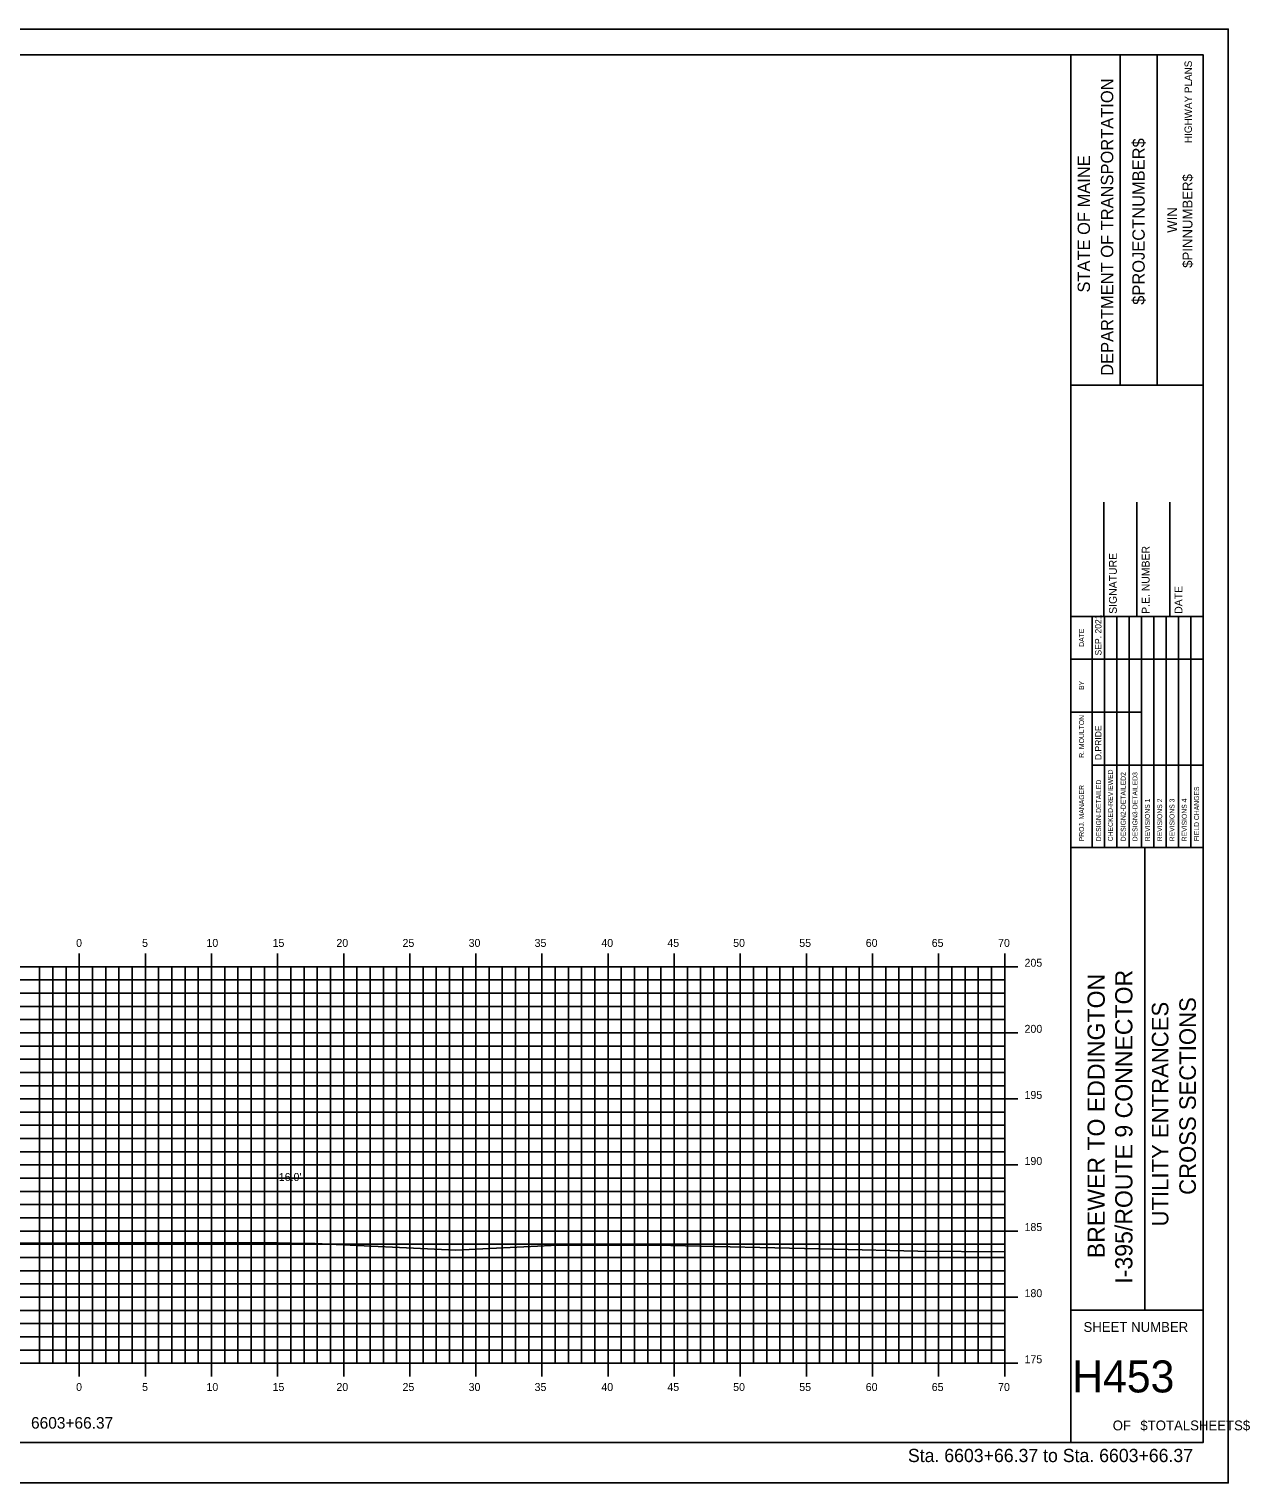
# Model space of a CAD drawing. Extents: x 1724848 to 1725020, y 459560 to 459670.
# Drawn here: x 1724927.7 to 1725020, y 459559.6 to 459669.6 of the extents above; entities that cross this region are included whole.
import ezdxf

# ---------------------------------------------------------------- set-up
doc = ezdxf.new("R2010")
doc.units = 0
for name, color, linetype in [('BORDER', 7, 'Continuous'), ('D_Roadway_SubGrade', 7, 'Continuous'), ('D_Text_Standard', 7, 'Continuous'), ('H_V ANNOTATION', 7, 'Continuous'), ('HIGHWAY_TITLE', 7, 'Continuous'), ('MAJOR', 7, 'Continuous'), ('MINOR', 7, 'Continuous'), ('PLOT BOUNDARY', 7, 'Continuous'), ('S_Roadway_Centerline', 7, 'Continuous')]:
    doc.layers.add(name, color=color, linetype=linetype)

msp = doc.modelspace()

# ---------------------------------------------------------------- linework, layer by layer
at = {"layer": 'BORDER'}
for p, q in [((1725006.5, 459562.61), (1725006.5, 459667.61)), ((1725010.23, 459642.61), (1725010.23, 459667.61)), ((1725013.02, 459642.61), (1725013.02, 459667.61)), ((1725006.5, 459642.61), (1725016.5, 459642.61)), ((1725009, 459625.12), (1725009, 459633.76)), ((1725011.5, 459625.12), (1725011.5, 459633.76)), ((1725014, 459625.12), (1725014, 459633.76)), ((1725006.5, 459625.12), (1725016.5, 459625.12)), ((1725006.5, 459607.62), (1725016.5, 459607.62)), ((1725012.09, 459572.62), (1725012.09, 459607.62)), ((1725006.5, 459572.62), (1725016.5, 459572.62))]:
    msp.add_line(p, q, dxfattribs=at)
msp.add_lwpolyline([(1724856.5, 459562.61), (1725016.5, 459562.61), (1725016.5, 459667.61), (1724856.5, 459667.61)], close=True, dxfattribs=at)
for points in [[(1725008.11, 459621.87), (1725008.11, 459625.12)], [(1725009.05, 459607.62), (1725009.05, 459625.12)], [(1725009.98, 459625.12), (1725009.98, 459607.62)], [(1725010.91, 459607.62), (1725010.91, 459625.12)], [(1725011.84, 459607.62), (1725011.84, 459625.12)], [(1725012.77, 459607.62), (1725012.77, 459625.12)], [(1725013.71, 459607.62), (1725013.71, 459625.12)], [(1725014.64, 459607.62), (1725014.64, 459625.12)], [(1725015.57, 459607.62), (1725015.57, 459625.12)], [(1725008.12, 459607.62), (1725008.12, 459624.41)], [(1725006.5, 459621.87), (1725016.5, 459621.87)], [(1725006.5, 459617.87), (1725008.12, 459617.87)], [(1725008.11, 459617.87), (1725011.84, 459617.87)], [(1725008.11, 459613.87), (1725016.5, 459613.87)]]:
    msp.add_lwpolyline(points, dxfattribs=at)
at = {"layer": 'D_Roadway_SubGrade'}
msp.add_line((1724946.5, 459577.72), (1724947.5, 459577.7), dxfattribs=at)
msp.add_lwpolyline([(1724931.5, 459577.71), (1724934.93, 459577.71), (1724945.04, 459577.73), (1724946.5, 459577.72)], dxfattribs=at)
at = {"layer": 'MAJOR'}
for p, q in [((1724931.5, 459599.61), (1724931.5, 459598.61)), ((1724936.5, 459599.61), (1724936.5, 459598.61)), ((1724941.5, 459599.61), (1724941.5, 459598.61)), ((1724946.5, 459599.61), (1724946.5, 459598.61)), ((1724951.5, 459599.61), (1724951.5, 459598.61)), ((1724956.5, 459599.61), (1724956.5, 459598.61)), ((1724961.5, 459599.61), (1724961.5, 459598.61)), ((1724966.5, 459599.61), (1724966.5, 459598.61)), ((1724971.5, 459599.61), (1724971.5, 459598.61)), ((1724976.5, 459599.61), (1724976.5, 459598.61)), ((1724981.5, 459599.61), (1724981.5, 459598.61)), ((1724986.5, 459599.61), (1724986.5, 459598.61)), ((1724991.5, 459599.61), (1724991.5, 459598.61)), ((1724996.5, 459599.61), (1724996.5, 459598.61)), ((1725001.5, 459599.61), (1725001.5, 459598.61)), ((1724861.5, 459598.61), (1725001.5, 459598.61)), ((1724861.5, 459598.61), (1725001.5, 459598.61)), ((1724931.5, 459568.61), (1724931.5, 459598.61)), ((1724936.5, 459568.61), (1724936.5, 459598.61)), ((1724941.5, 459568.61), (1724941.5, 459598.61)), ((1724946.5, 459568.61), (1724946.5, 459598.61)), ((1724951.5, 459568.61), (1724951.5, 459598.61)), ((1724956.5, 459568.61), (1724956.5, 459598.61)), ((1724961.5, 459568.61), (1724961.5, 459598.61)), ((1724966.5, 459568.61), (1724966.5, 459598.61)), ((1724971.5, 459568.61), (1724971.5, 459598.61)), ((1724976.5, 459568.61), (1724976.5, 459598.61)), ((1724981.5, 459568.61), (1724981.5, 459598.61)), ((1724986.5, 459568.61), (1724986.5, 459598.61)), ((1724991.5, 459568.61), (1724991.5, 459598.61)), ((1724996.5, 459568.61), (1724996.5, 459598.61)), ((1725002.5, 459598.61), (1725000.5, 459598.61)), ((1725001.5, 459568.61), (1725001.5, 459598.61)), ((1725001.5, 459568.61), (1725001.5, 459598.61)), ((1724861.5, 459593.61), (1725001.5, 459593.61)), ((1725002.5, 459593.61), (1725000.5, 459593.61)), ((1724861.5, 459588.61), (1725001.5, 459588.61)), ((1725002.5, 459588.61), (1725000.5, 459588.61)), ((1724861.5, 459583.61), (1725001.5, 459583.61)), ((1725002.5, 459583.61), (1725000.5, 459583.61)), ((1724861.5, 459578.61), (1725001.5, 459578.61)), ((1725002.5, 459578.61), (1725000.5, 459578.61)), ((1724861.5, 459573.61), (1725001.5, 459573.61)), ((1725002.5, 459573.61), (1725000.5, 459573.61)), ((1724861.5, 459568.61), (1725001.5, 459568.61)), ((1724861.5, 459568.61), (1725001.5, 459568.61)), ((1724931.5, 459567.61), (1724931.5, 459568.61)), ((1724936.5, 459567.61), (1724936.5, 459568.61)), ((1724941.5, 459567.61), (1724941.5, 459568.61)), ((1724946.5, 459567.61), (1724946.5, 459568.61)), ((1724951.5, 459567.61), (1724951.5, 459568.61)), ((1724956.5, 459567.61), (1724956.5, 459568.61)), ((1724961.5, 459567.61), (1724961.5, 459568.61)), ((1724966.5, 459567.61), (1724966.5, 459568.61)), ((1724971.5, 459567.61), (1724971.5, 459568.61)), ((1724976.5, 459567.61), (1724976.5, 459568.61)), ((1724981.5, 459567.61), (1724981.5, 459568.61)), ((1724986.5, 459567.61), (1724986.5, 459568.61)), ((1724991.5, 459567.61), (1724991.5, 459568.61)), ((1724996.5, 459567.61), (1724996.5, 459568.61)), ((1725002.5, 459568.61), (1725000.5, 459568.61)), ((1725001.5, 459567.61), (1725001.5, 459568.61))]:
    msp.add_line(p, q, dxfattribs=at)
at = {"layer": 'MINOR'}
for p, q in [((1724861.5, 459597.61), (1725001.5, 459597.61)), ((1724928.5, 459568.61), (1724928.5, 459598.61)), ((1724929.5, 459568.61), (1724929.5, 459598.61)), ((1724930.5, 459568.61), (1724930.5, 459598.61)), ((1724932.5, 459568.61), (1724932.5, 459598.61)), ((1724933.5, 459568.61), (1724933.5, 459598.61)), ((1724934.5, 459568.61), (1724934.5, 459598.61)), ((1724935.5, 459568.61), (1724935.5, 459598.61)), ((1724937.5, 459568.61), (1724937.5, 459598.61)), ((1724938.5, 459568.61), (1724938.5, 459598.61)), ((1724939.5, 459568.61), (1724939.5, 459598.61)), ((1724940.5, 459568.61), (1724940.5, 459598.61)), ((1724942.5, 459568.61), (1724942.5, 459598.61)), ((1724943.5, 459568.61), (1724943.5, 459598.61)), ((1724944.5, 459568.61), (1724944.5, 459598.61)), ((1724945.5, 459568.61), (1724945.5, 459598.61)), ((1724947.5, 459568.61), (1724947.5, 459598.61)), ((1724948.5, 459568.61), (1724948.5, 459598.61)), ((1724949.5, 459568.61), (1724949.5, 459598.61)), ((1724950.5, 459568.61), (1724950.5, 459598.61)), ((1724952.5, 459568.61), (1724952.5, 459598.61)), ((1724953.5, 459568.61), (1724953.5, 459598.61)), ((1724954.5, 459568.61), (1724954.5, 459598.61)), ((1724955.5, 459568.61), (1724955.5, 459598.61)), ((1724957.5, 459568.61), (1724957.5, 459598.61)), ((1724958.5, 459568.61), (1724958.5, 459598.61)), ((1724959.5, 459568.61), (1724959.5, 459598.61)), ((1724960.5, 459568.61), (1724960.5, 459598.61)), ((1724962.5, 459568.61), (1724962.5, 459598.61)), ((1724963.5, 459568.61), (1724963.5, 459598.61)), ((1724964.5, 459568.61), (1724964.5, 459598.61)), ((1724965.5, 459568.61), (1724965.5, 459598.61)), ((1724967.5, 459568.61), (1724967.5, 459598.61)), ((1724968.5, 459568.61), (1724968.5, 459598.61)), ((1724969.5, 459568.61), (1724969.5, 459598.61)), ((1724970.5, 459568.61), (1724970.5, 459598.61)), ((1724972.5, 459568.61), (1724972.5, 459598.61)), ((1724973.5, 459568.61), (1724973.5, 459598.61)), ((1724974.5, 459568.61), (1724974.5, 459598.61)), ((1724975.5, 459568.61), (1724975.5, 459598.61)), ((1724977.5, 459568.61), (1724977.5, 459598.61)), ((1724978.5, 459568.61), (1724978.5, 459598.61)), ((1724979.5, 459568.61), (1724979.5, 459598.61)), ((1724980.5, 459568.61), (1724980.5, 459598.61)), ((1724982.5, 459568.61), (1724982.5, 459598.61)), ((1724983.5, 459568.61), (1724983.5, 459598.61)), ((1724984.5, 459568.61), (1724984.5, 459598.61)), ((1724985.5, 459568.61), (1724985.5, 459598.61)), ((1724987.5, 459568.61), (1724987.5, 459598.61)), ((1724988.5, 459568.61), (1724988.5, 459598.61)), ((1724989.5, 459568.61), (1724989.5, 459598.61)), ((1724990.5, 459568.61), (1724990.5, 459598.61)), ((1724992.5, 459568.61), (1724992.5, 459598.61)), ((1724993.5, 459568.61), (1724993.5, 459598.61)), ((1724994.5, 459568.61), (1724994.5, 459598.61)), ((1724995.5, 459568.61), (1724995.5, 459598.61)), ((1724997.5, 459568.61), (1724997.5, 459598.61)), ((1724998.5, 459568.61), (1724998.5, 459598.61)), ((1724999.5, 459568.61), (1724999.5, 459598.61)), ((1725000.5, 459568.61), (1725000.5, 459598.61)), ((1725001.5, 459597.61), (1725000.5, 459597.61)), ((1724861.5, 459596.61), (1725001.5, 459596.61)), ((1725001.5, 459596.61), (1725000.5, 459596.61)), ((1724861.5, 459595.61), (1725001.5, 459595.61)), ((1725001.5, 459595.61), (1725000.5, 459595.61)), ((1724861.5, 459594.61), (1725001.5, 459594.61)), ((1725001.5, 459594.61), (1725000.5, 459594.61)), ((1724861.5, 459592.61), (1725001.5, 459592.61)), ((1725001.5, 459592.61), (1725000.5, 459592.61)), ((1724861.5, 459591.61), (1725001.5, 459591.61)), ((1725001.5, 459591.61), (1725000.5, 459591.61)), ((1724861.5, 459590.61), (1725001.5, 459590.61)), ((1725001.5, 459590.61), (1725000.5, 459590.61)), ((1724861.5, 459589.61), (1725001.5, 459589.61)), ((1725001.5, 459589.61), (1725000.5, 459589.61)), ((1724861.5, 459587.61), (1725001.5, 459587.61)), ((1724861.5, 459586.61), (1725001.5, 459586.61)), ((1725001.5, 459587.61), (1725000.5, 459587.61)), ((1725001.5, 459586.61), (1725000.5, 459586.61)), ((1724861.5, 459585.61), (1725001.5, 459585.61)), ((1725001.5, 459585.61), (1725000.5, 459585.61)), ((1724861.5, 459584.61), (1725001.5, 459584.61)), ((1725001.5, 459584.61), (1725000.5, 459584.61)), ((1724861.5, 459582.61), (1725001.5, 459582.61)), ((1725001.5, 459582.61), (1725000.5, 459582.61)), ((1724861.5, 459581.61), (1725001.5, 459581.61)), ((1725001.5, 459581.61), (1725000.5, 459581.61)), ((1724861.5, 459580.61), (1725001.5, 459580.61)), ((1725001.5, 459580.61), (1725000.5, 459580.61)), ((1724861.5, 459579.61), (1725001.5, 459579.61)), ((1725001.5, 459579.61), (1725000.5, 459579.61)), ((1724861.5, 459577.61), (1725001.5, 459577.61)), ((1725001.5, 459577.61), (1725000.5, 459577.61)), ((1724861.5, 459576.61), (1725001.5, 459576.61)), ((1724861.5, 459575.61), (1725001.5, 459575.61)), ((1725001.5, 459576.61), (1725000.5, 459576.61)), ((1725001.5, 459575.61), (1725000.5, 459575.61)), ((1724861.5, 459574.61), (1725001.5, 459574.61)), ((1725001.5, 459574.61), (1725000.5, 459574.61)), ((1724861.5, 459572.61), (1725001.5, 459572.61)), ((1725001.5, 459572.61), (1725000.5, 459572.61)), ((1724861.5, 459571.61), (1725001.5, 459571.61)), ((1725001.5, 459571.61), (1725000.5, 459571.61)), ((1724861.5, 459570.61), (1725001.5, 459570.61)), ((1725001.5, 459570.61), (1725000.5, 459570.61)), ((1724861.5, 459569.61), (1725001.5, 459569.61)), ((1725001.5, 459569.61), (1725000.5, 459569.61))]:
    msp.add_line(p, q, dxfattribs=at)
at = {"layer": 'PLOT BOUNDARY'}
msp.add_lwpolyline([(1724848.41, 459559.55), (1725018.41, 459559.55), (1725018.41, 459669.55), (1724848.41, 459669.55)], close=True, dxfattribs=at)
at = {"layer": 'S_Roadway_Centerline'}
msp.add_lwpolyline([(1724861.5, 459578.62), (1724862.22, 459578.63), (1724866.37, 459578.56), (1724883.95, 459578.02), (1724889.86, 459577.92), (1724897.91, 459578), (1724903.58, 459577.95), (1724912.22, 459577.75), (1724924.38, 459577.7), (1724924.82, 459577.69), (1724945.04, 459577.73), (1724949.34, 459577.68), (1724959.96, 459577.17), (1724967.19, 459577.52), (1724975.1, 459577.53), (1724988.6, 459577.24), (1724994.92, 459577.09), (1725001.5, 459577.04)], dxfattribs=at)

# ---------------------------------------------------------------- texts
at = {"layer": 'BORDER'}
for s, height, p in [('DEPARTMENT OF TRANSPORTATION', 0.9318, (1725009.71, 459643.32)), ('$PROJECTNUMBER$', 0.9318, (1725012.09, 459648.69)), ('STATE OF MAINE', 0.9318, (1725007.95, 459649.62)), ('$PINNUMBER$', 0.7453, (1725015.7, 459651.49)), ('WIN', 0.745, (1725014.54, 459654.14)), ('SIGNATURE', 0.591, (1725009.98, 459625.31)), ('P.E. NUMBER', 0.5906, (1725012.46, 459625.31)), ('DATE', 0.591, (1725014.94, 459625.31)), ('SEP. 2021', 0.485, (1725008.82, 459622.16)), ('DATE', 0.371, (1725007.5, 459622.82)), ('BY', 0.371, (1725007.5, 459619.55)), ('R. MOULTON', 0.373, (1725007.5, 459614.42)), ('D.PRIDE', 0.485, (1725008.82, 459614.24)), ('CHECKED-REVIEWED', 0.3727, (1725009.68, 459608.1)), ('DESIGN2-DETAILED2', 0.3727, (1725010.65, 459608.1)), ('DESIGN3-DETAILED3', 0.3727, (1725011.54, 459608.1)), ('PROJ. MANAGER', 0.3727, (1725007.5, 459608.1)), ('DESIGN-DETAILED', 0.3727, (1725008.79, 459608.1)), ('FIELD CHANGES', 0.3727, (1725016.2, 459608.1)), ('REVISIONS 1', 0.3727, (1725012.48, 459608.1)), ('REVISIONS 2', 0.3727, (1725013.41, 459608.1)), ('REVISIONS 3', 0.3727, (1725014.34, 459608.1)), ('REVISIONS 4', 0.3727, (1725015.27, 459608.1)), ('UTILITY ENTRANCES', 1.25, (1725013.88, 459578.96)), ('CROSS SECTIONS', 1.25, (1725015.96, 459581.35))]:
    msp.add_text(s, height=height, rotation=90, dxfattribs=at).set_placement(p)
for s, height, p in [('SHEET NUMBER', 0.7453, (1725007.46, 459570.98)), ('H453', 2.419, (1725006.6, 459566.4)), ('OF', 0.745, (1725009.67, 459563.53)), ('$TOTALSHEETS$', 0.7453, (1725011.76, 459563.53))]:
    msp.add_text(s, height=height, dxfattribs=at).set_placement(p)
at = {"layer": 'D_Text_Standard'}
msp.add_text("16.0'", height=0.6, dxfattribs=at).set_placement((1724946.59, 459582.4))
at = {"layer": 'H_V ANNOTATION'}
for s, height, p in [('0', 0.6, (1724931.26, 459600.11)), ('5', 0.6, (1724936.25, 459600.11)), ('10', 0.6, (1724941.12, 459600.11)), ('15', 0.6, (1724946.12, 459600.11)), ('20', 0.6, (1724950.95, 459600.11)), ('25', 0.6, (1724955.95, 459600.11)), ('30', 0.6, (1724960.95, 459600.11)), ('35', 0.6, (1724965.94, 459600.11)), ('40', 0.6, (1724970.99, 459600.11)), ('45', 0.6, (1724975.98, 459600.11)), ('50', 0.6, (1724980.96, 459600.11)), ('55', 0.6, (1724985.96, 459600.11)), ('60', 0.6, (1724990.99, 459600.11)), ('65', 0.6, (1724995.98, 459600.11)), ('70', 0.6, (1725001, 459600.11)), ('205', 0.6, (1725003, 459598.61)), ('200', 0.6, (1725003, 459593.61)), ('195', 0.6, (1725003, 459588.61)), ('190', 0.6, (1725003, 459583.61)), ('185', 0.6, (1725003, 459578.61)), ('180', 0.6, (1725003, 459573.61)), ('175', 0.6, (1725003, 459568.61)), ('0', 0.6, (1724931.26, 459566.51)), ('5', 0.6, (1724936.25, 459566.51)), ('10', 0.6, (1724941.12, 459566.51)), ('15', 0.6, (1724946.12, 459566.51)), ('20', 0.6, (1724950.95, 459566.51)), ('25', 0.6, (1724955.95, 459566.51)), ('30', 0.6, (1724960.95, 459566.51)), ('35', 0.6, (1724965.94, 459566.51)), ('40', 0.6, (1724970.99, 459566.51)), ('45', 0.6, (1724975.98, 459566.51)), ('50', 0.6, (1724980.96, 459566.51)), ('55', 0.6, (1724985.96, 459566.51)), ('60', 0.6, (1724990.99, 459566.51)), ('65', 0.6, (1724995.98, 459566.51)), ('70', 0.6, (1725001, 459566.51)), ('6603+66.37', 0.875, (1724927.85, 459563.66)), ('Sta. 6603+66.37 to Sta. 6603+66.37', 1.0002, (1724994.18, 459561.13))]:
    msp.add_text(s, height=height, dxfattribs=at).set_placement(p)
at = {"layer": 'HIGHWAY_TITLE'}
for s, height, p in [('HIGHWAY PLANS', 0.559, (1725015.66, 459660.93)), ('BREWER TO EDDINGTON', 1.3043, (1725009.07, 459576.56)), ('I-395/ROUTE 9 CONNECTOR', 1.3043, (1725011.16, 459574.63))]:
    msp.add_text(s, height=height, rotation=90, dxfattribs=at).set_placement(p)

doc.saveas('drawing.dxf')
